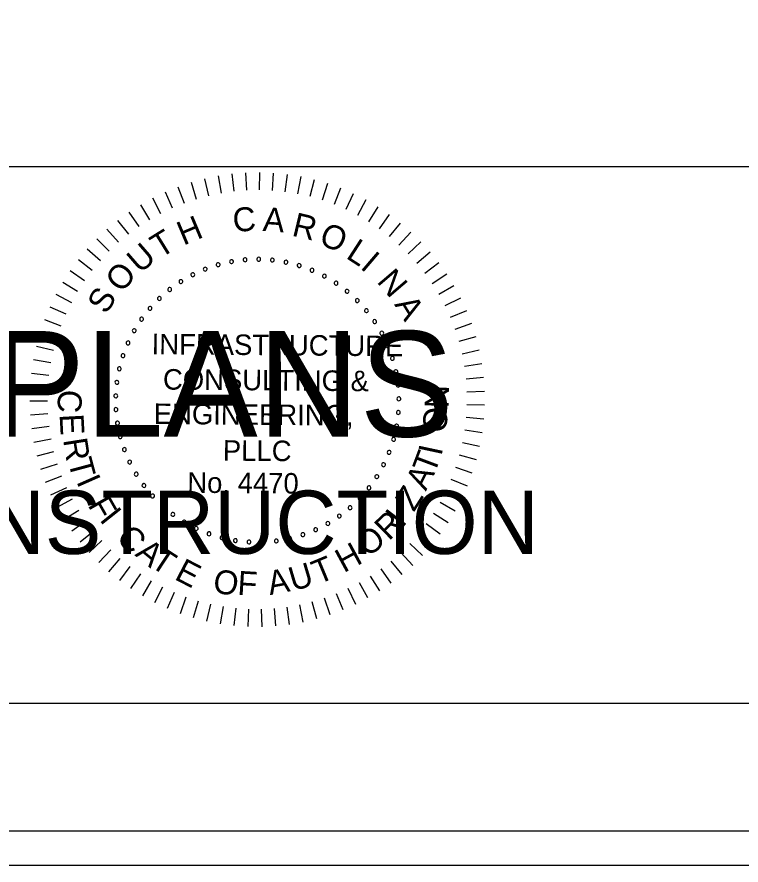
# Model space of a CAD drawing. Extents: x 967 to 1326, y 964 to 2584.
# Drawn here: x 1189.3 to 1212.88, y 2363.72 to 2391.36 of the extents above; entities that cross this region are included whole.
import ezdxf

# ---------------------------------------------------------------- set-up
doc = ezdxf.new("R2010")
doc.units = 0
for name, color, linetype in [('RD_SHT_Bndy', 7, 'Continuous'), ('RD_SHT_IplotShp', 7, 'Continuous'), ('RD_SHT_Misc1', 7, 'Continuous'), ('RD_SHT_Misc2', 7, 'Continuous'), ('RD_Sketch1', 7, 'Continuous')]:
    doc.layers.add(name, color=color, linetype=linetype)

msp = doc.modelspace()

# ---------------------------------------------------------------- linework, layer by layer
at = {"layer": 'RD_SHT_Bndy'}
for p, q in [((996.114, 2386.486), (1323.886, 2386.486)), ((1323.886, 2368.983), (996.114, 2368.983))]:
    msp.add_line(p, q, dxfattribs=at)
at = {"layer": 'RD_SHT_IplotShp'}
for points in [[(967.409, 2363.72), (1326.285, 2363.72), (1326.285, 2583.72), (967.409, 2583.72)], [(988.525, 2364.84), (1326.285, 2364.84), (1326.285, 2582.6), (988.525, 2582.6)]]:
    msp.add_lwpolyline(points, close=True, dxfattribs=at)
at = {"layer": 'RD_SHT_Misc1'}
for p, q in [((1195.846, 2386.181), (1195.945, 2385.62)), ((1196.292, 2386.245), (1196.357, 2385.68)), ((1196.742, 2386.282), (1196.772, 2385.714)), ((1197.194, 2386.292), (1197.189, 2385.723)), ((1197.645, 2386.274), (1197.606, 2385.706)), ((1198.094, 2386.228), (1198.02, 2385.664)), ((1198.54, 2386.156), (1198.432, 2385.596)), ((1194.968, 2385.971), (1195.134, 2385.427)), ((1195.403, 2386.09), (1195.536, 2385.536)), ((1198.98, 2386.056), (1198.838, 2385.504)), ((1199.414, 2385.929), (1199.238, 2385.387)), ((1194.122, 2385.656), (1194.353, 2385.136)), ((1194.54, 2385.827), (1194.739, 2385.293)), ((1199.839, 2385.777), (1199.63, 2385.246)), ((1200.253, 2385.598), (1200.013, 2385.082)), ((1193.715, 2385.461), (1193.978, 2384.956)), ((1200.656, 2385.395), (1200.385, 2384.894)), ((1193.321, 2385.241), (1193.614, 2384.752)), ((1201.047, 2385.167), (1200.745, 2384.684)), ((1192.94, 2384.997), (1193.263, 2384.528)), ((1201.422, 2384.917), (1201.092, 2384.453)), ((1192.576, 2384.731), (1192.926, 2384.282)), ((1201.781, 2384.643), (1201.424, 2384.2)), ((1192.228, 2384.443), (1192.605, 2384.016)), ((1202.124, 2384.349), (1201.739, 2383.928)), ((1191.899, 2384.134), (1192.301, 2383.731)), ((1202.447, 2384.034), (1202.038, 2383.638)), ((1191.589, 2383.805), (1192.015, 2383.428)), ((1202.751, 2383.7), (1202.318, 2383.329)), ((1191.299, 2383.459), (1191.748, 2383.108)), ((1203.034, 2383.348), (1202.579, 2383.004)), ((1191.032, 2383.095), (1191.501, 2382.772)), ((1203.294, 2382.979), (1202.82, 2382.664)), ((1190.787, 2382.716), (1191.274, 2382.422)), ((1203.532, 2382.595), (1203.04, 2382.31)), ((1190.565, 2382.323), (1191.07, 2382.059)), ((1203.746, 2382.198), (1203.237, 2381.943)), ((1190.368, 2381.916), (1190.888, 2381.684)), ((1203.936, 2381.788), (1203.412, 2381.564)), ((1190.196, 2381.499), (1190.729, 2381.299)), ((1204.1, 2381.367), (1203.563, 2381.176)), ((1190.05, 2381.072), (1190.594, 2380.905)), ((1204.238, 2380.937), (1203.691, 2380.779)), ((1189.93, 2380.636), (1190.484, 2380.503)), ((1204.349, 2380.5), (1203.794, 2380.375)), ((1189.837, 2380.195), (1190.398, 2380.095)), ((1204.434, 2380.056), (1203.872, 2379.966)), ((1189.771, 2379.748), (1190.337, 2379.683)), ((1204.491, 2379.608), (1203.925, 2379.552)), ((1189.732, 2379.298), (1190.301, 2379.267)), ((1204.522, 2379.158), (1203.953, 2379.137)), ((1189.721, 2378.847), (1190.29, 2378.851)), ((1204.524, 2378.706), (1203.955, 2378.72)), ((1189.737, 2378.396), (1190.306, 2378.434)), ((1204.499, 2378.256), (1203.932, 2378.304)), ((1189.781, 2377.946), (1190.346, 2378.019)), ((1204.447, 2377.807), (1203.884, 2377.89)), ((1189.852, 2377.5), (1190.412, 2377.608)), ((1204.367, 2377.363), (1203.81, 2377.479)), ((1189.951, 2377.06), (1190.502, 2377.201)), ((1204.261, 2376.924), (1203.712, 2377.074)), ((1190.076, 2376.626), (1190.617, 2376.8)), ((1204.128, 2376.492), (1203.589, 2376.676)), ((1190.227, 2376.2), (1190.757, 2376.408)), ((1203.969, 2376.07), (1203.442, 2376.286)), ((1190.403, 2375.785), (1190.92, 2376.024)), ((1190.605, 2375.381), (1191.106, 2375.651)), ((1203.784, 2375.658), (1203.271, 2375.906)), ((1203.574, 2375.258), (1203.078, 2375.537)), ((1190.831, 2374.99), (1191.315, 2375.291)), ((1203.341, 2374.871), (1202.862, 2375.18)), ((1191.081, 2374.614), (1191.545, 2374.943)), ((1203.085, 2374.5), (1202.626, 2374.837)), ((1191.353, 2374.253), (1191.796, 2374.61)), ((1191.646, 2373.91), (1192.067, 2374.293)), ((1202.806, 2374.145), (1202.368, 2374.509)), ((1191.96, 2373.585), (1192.356, 2373.994)), ((1202.506, 2373.807), (1202.092, 2374.197)), ((1192.293, 2373.28), (1192.664, 2373.712)), ((1202.186, 2373.488), (1201.796, 2373.903)), ((1192.644, 2372.996), (1192.988, 2373.45)), ((1201.847, 2373.19), (1201.484, 2373.628)), ((1193.011, 2372.734), (1193.327, 2373.208)), ((1201.491, 2372.912), (1201.155, 2373.372)), ((1193.394, 2372.495), (1193.68, 2372.987)), ((1200.731, 2372.425), (1200.453, 2372.922)), ((1201.119, 2372.657), (1200.811, 2373.136)), ((1193.791, 2372.279), (1194.047, 2372.788)), ((1194.2, 2372.088), (1194.424, 2372.612)), ((1200.331, 2372.217), (1200.083, 2372.73)), ((1194.62, 2371.923), (1194.812, 2372.459)), ((1195.05, 2371.783), (1195.208, 2372.33)), ((1199.495, 2371.877), (1199.312, 2372.416)), ((1199.918, 2372.034), (1199.702, 2372.561)), ((1195.487, 2371.67), (1195.612, 2372.225)), ((1195.93, 2371.584), (1196.021, 2372.146)), ((1196.377, 2371.524), (1196.434, 2372.091)), ((1196.828, 2371.493), (1196.85, 2372.062)), ((1197.279, 2371.488), (1197.267, 2372.058)), ((1197.73, 2371.512), (1197.683, 2372.079)), ((1198.179, 2371.562), (1198.097, 2372.126)), ((1198.624, 2371.64), (1198.508, 2372.198)), ((1199.063, 2371.745), (1198.913, 2372.295))]:
    msp.add_line(p, q, dxfattribs=at)
for centre, start, end in [((1196.285, 2383.388), 10.6038, 190.6038), ((1196.285, 2383.388), 190.6038, 10.6038), ((1196.727, 2383.447), 5.0653, 185.0653), ((1196.727, 2383.447), 185.0653, 5.0653), ((1197.172, 2383.464), 359.5268, 179.5268), ((1197.172, 2383.464), 179.5268, 359.5268), ((1197.617, 2383.438), 173.9884, 353.9884), ((1197.617, 2383.438), 353.9884, 173.9884), ((1198.057, 2383.369), 168.4499, 348.4499), ((1198.057, 2383.369), 348.4499, 168.4499), ((1195.429, 2383.142), 21.6807, 201.6807), ((1195.429, 2383.142), 201.6807, 21.6807), ((1195.851, 2383.285), 16.1422, 196.1422), ((1195.851, 2383.285), 196.1422, 16.1422), ((1198.489, 2383.258), 162.9114, 342.9114), ((1198.489, 2383.258), 342.9114, 162.9114), ((1198.908, 2383.106), 157.373, 337.373), ((1198.908, 2383.106), 337.373, 157.373), ((1195.023, 2382.958), 27.2191, 207.2191), ((1195.023, 2382.958), 207.2191, 27.2191), ((1199.31, 2382.914), 151.8345, 331.8345), ((1199.31, 2382.914), 331.8345, 151.8345), ((1194.637, 2382.736), 32.7576, 212.7576), ((1194.637, 2382.736), 212.7576, 32.7576), ((1199.692, 2382.684), 146.2961, 326.2961), ((1199.692, 2382.684), 326.2961, 146.2961), ((1194.274, 2382.478), 38.2961, 218.2961), ((1194.274, 2382.478), 218.2961, 38.2961), ((1200.05, 2382.419), 140.7576, 320.7576), ((1200.05, 2382.419), 320.7576, 140.7576), ((1193.937, 2382.186), 43.8345, 223.8345), ((1193.937, 2382.186), 223.8345, 43.8345), ((1200.38, 2382.12), 135.2191, 315.2191), ((1200.38, 2382.12), 315.2191, 135.2191), ((1193.63, 2381.862), 49.373, 229.373), ((1193.63, 2381.862), 229.373, 49.373), ((1200.68, 2381.79), 129.6807, 309.6807), ((1200.68, 2381.79), 309.6807, 129.6807), ((1193.356, 2381.511), 54.9114, 234.9114), ((1193.356, 2381.511), 234.9114, 54.9114), ((1200.947, 2381.433), 124.1422, 304.1422), ((1200.947, 2381.433), 304.1422, 124.1422), ((1193.117, 2381.135), 60.4499, 240.4499), ((1193.117, 2381.135), 240.4499, 60.4499), ((1201.179, 2381.052), 118.6038, 298.6038), ((1201.179, 2381.052), 298.6038, 118.6038), ((1192.915, 2380.737), 65.9884, 245.9884), ((1192.915, 2380.737), 245.9884, 65.9884), ((1201.372, 2380.651), 113.0653, 293.0653), ((1201.372, 2380.651), 293.0653, 113.0653), ((1192.753, 2380.322), 71.5268, 251.5268), ((1192.753, 2380.322), 251.5268, 71.5268), ((1201.526, 2380.233), 107.5268, 287.5268), ((1201.526, 2380.233), 287.5268, 107.5268), ((1192.632, 2379.894), 77.0653, 257.0653), ((1192.632, 2379.894), 257.0653, 77.0653), ((1201.638, 2379.801), 101.9884, 281.9884), ((1201.638, 2379.801), 281.9884, 101.9884), ((1192.552, 2379.455), 82.6038, 262.6038), ((1192.552, 2379.455), 262.6038, 82.6038), ((1201.709, 2379.361), 96.4499, 276.4499), ((1201.709, 2379.361), 276.4499, 96.4499), ((1192.515, 2379.011), 88.1422, 268.1422), ((1192.515, 2379.011), 268.1422, 88.1422), ((1201.737, 2378.917), 90.9114, 270.9114), ((1201.737, 2378.917), 270.9114, 90.9114), ((1192.522, 2378.565), 93.6807, 273.6807), ((1192.522, 2378.565), 273.6807, 93.6807), ((1201.721, 2378.471), 85.373, 265.373), ((1201.721, 2378.471), 265.373, 85.373), ((1192.571, 2378.122), 99.2191, 279.2191), ((1192.571, 2378.122), 279.2191, 99.2191), ((1201.663, 2378.029), 79.8345, 259.8345), ((1201.663, 2378.029), 259.8345, 79.8345), ((1192.662, 2377.686), 104.7576, 284.7576), ((1192.662, 2377.686), 284.7576, 104.7576), ((1201.563, 2377.595), 74.2961, 254.2961), ((1201.563, 2377.595), 254.2961, 74.2961), ((1192.796, 2377.261), 110.2961, 290.2961), ((1192.796, 2377.261), 290.2961, 110.2961), ((1201.42, 2377.173), 68.7576, 248.7576), ((1201.42, 2377.173), 248.7576, 68.7576), ((1192.97, 2376.851), 115.8345, 295.8345), ((1192.97, 2376.851), 295.8345, 115.8345), ((1201.238, 2376.766), 63.2191, 243.2191), ((1201.238, 2376.766), 243.2191, 63.2191), ((1193.182, 2376.459), 121.373, 301.373), ((1193.182, 2376.459), 301.373, 121.373), ((1201.018, 2376.379), 57.6807, 237.6807), ((1201.018, 2376.379), 237.6807, 57.6807), ((1193.432, 2376.09), 126.9114, 306.9114), ((1193.432, 2376.09), 306.9114, 126.9114), ((1200.761, 2376.014), 52.1422, 232.1422), ((1200.761, 2376.014), 232.1422, 52.1422), ((1193.715, 2375.746), 132.4499, 312.4499), ((1193.715, 2375.746), 312.4499, 132.4499), ((1200.47, 2375.677), 46.6038, 226.6038), ((1200.47, 2375.677), 226.6038, 46.6038), ((1194.031, 2375.431), 137.9884, 317.9884), ((1194.031, 2375.431), 317.9884, 137.9884), ((1200.148, 2375.369), 41.0653, 221.0653), ((1200.148, 2375.369), 221.0653, 41.0653), ((1194.376, 2375.149), 143.5268, 323.5268), ((1194.376, 2375.149), 323.5268, 143.5268), ((1199.798, 2375.093), 35.5268, 215.5268), ((1199.798, 2375.093), 215.5268, 35.5268), ((1194.746, 2374.901), 149.0653, 329.0653), ((1194.746, 2374.901), 329.0653, 149.0653), ((1199.422, 2374.853), 29.9884, 209.9884), ((1199.422, 2374.853), 209.9884, 29.9884), ((1195.139, 2374.69), 154.6038, 334.6038), ((1195.139, 2374.69), 334.6038, 154.6038), ((1195.55, 2374.517), 160.1422, 340.1422), ((1195.55, 2374.517), 340.1422, 160.1422), ((1198.611, 2374.486), 18.9114, 198.9114), ((1199.026, 2374.65), 24.4499, 204.4499), ((1199.026, 2374.65), 204.4499, 24.4499), ((1195.975, 2374.386), 165.6807, 345.6807), ((1195.975, 2374.386), 345.6807, 165.6807), ((1196.412, 2374.295), 171.2191, 351.2191), ((1196.412, 2374.295), 351.2191, 171.2191), ((1196.855, 2374.248), 356.7576, 176.7576), ((1197.301, 2374.243), 2.2961, 182.2961), ((1197.745, 2374.282), 7.8345, 187.8345), ((1197.745, 2374.282), 187.8345, 7.8345), ((1198.183, 2374.363), 13.373, 193.373), ((1198.183, 2374.363), 193.373, 13.373), ((1198.611, 2374.486), 198.9114, 18.9114), ((1196.855, 2374.248), 176.7576, 356.7576), ((1197.301, 2374.243), 182.2961, 2.2961)]:
    msp.add_arc(centre, 0.0627, start, end, dxfattribs=at)
at = {"layer": 'RD_Sketch1'}
msp.add_lwpolyline([(967.409, 2363.72), (1326.285, 2363.72), (1326.285, 2583.72), (967.409, 2583.72)], close=True, dxfattribs=at)

# ---------------------------------------------------------------- texts
at = {"layer": 'RD_SHT_Misc1'}
for s, height, rotation, p in [('C', 0.78, 4.7281, (1196.355, 2384.346)), ('A', 0.78, 355.6981, (1197.29, 2384.39)), ('H', 0.78, 22.7882, (1194.72, 2383.904)), ('R', 0.78, 346.6681, (1198.222, 2384.238)), ('O', 0.78, 337.638, (1199.096, 2383.972)), ('T', 0.78, 31.8182, (1193.961, 2383.478)), ('U', 0.78, 40.8482, (1193.306, 2382.976)), ('L', 0.78, 327.108, (1199.981, 2383.52)), ('I', 0.78, 319.578, (1200.451, 2383.182)), ('O', 0.78, 49.8782, (1192.707, 2382.341)), ('N', 0.78, 310.548, (1200.994, 2382.728)), ('S', 0.78, 58.9083, (1192.211, 2381.642)), ('A', 0.78, 301.5179, (1201.576, 2381.991)), ('INFRASTRUCTURE', 0.66873, 359.5268, (1193.682, 2380.367)), ('CONSULTING &', 0.66873, 359.5268, (1194.051, 2379.217)), ('N', 0.78, 89.2085, (1203.359, 2378.604)), ('C', 0.78, 267.025, (1190.646, 2379.227)), ('ENGINEERING,', 0.66873, 359.5268, (1193.751, 2378.095)), ('O', 0.78, 83.2085, (1203.26, 2377.786)), ('E', 0.78, 273.025, (1190.685, 2378.408)), ('R', 0.78, 279.025, (1190.799, 2377.583)), ('PLLC', 0.6687, 359.5268, (1196.002, 2376.9)), ('I', 0.78, 77.9093, (1203.121, 2377.032)), ('T', 0.78, 285.025, (1190.955, 2376.878)), ('T', 0.78, 69.3954, (1202.891, 2376.428)), ('No. 4470', 0.6687, 359.5268, (1194.843, 2375.855)), ('A', 0.78, 63.3954, (1202.616, 2375.888)), ('I', 0.78, 293.7713, (1191.221, 2376.225)), ('Z', 0.78, 57.3954, (1202.224, 2375.206)), ('F', 0.78, 299.7713, (1191.589, 2375.455)), ('I', 0.78, 308.5268, (1191.965, 2374.973)), ('R', 0.78, 44.5268, (1201.415, 2374.267)), ('I', 0.78, 52.3339, (1201.856, 2374.69)), ('C', 0.78, 314.5268, (1192.496, 2374.346)), ('O', 0.78, 38.5268, (1200.73, 2373.731)), ('A', 0.78, 320.5268, (1193.115, 2373.822)), ('T', 0.78, 326.5268, (1193.602, 2373.478)), ('H', 0.78, 28.5268, (1199.942, 2373.23)), ('E', 0.78, 332.5268, (1194.394, 2373.051)), ('T', 0.78, 22.5268, (1199.108, 2372.856)), ('U', 0.78, 16.5268, (1198.288, 2372.638)), ('O', 0.78, 350.5268, (1195.647, 2372.614)), ('F', 0.78, 356.5268, (1196.465, 2372.532)), ('A', 0.78, 10.5268, (1197.537, 2372.517))]:
    msp.add_text(s, height=height, rotation=rotation, dxfattribs=at).set_placement(p)
at = {"layer": 'RD_SHT_Misc2'}
for s, height, p in [('FINAL PLANS', 3.4375, (1174.145, 2377.685)), ('NOT FOR CONSTRUCTION', 2.0625, (1170.901, 2373.86))]:
    msp.add_text(s, height=height, dxfattribs=at).set_placement(p)

doc.saveas('drawing.dxf')
